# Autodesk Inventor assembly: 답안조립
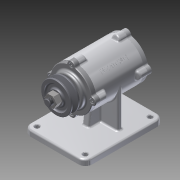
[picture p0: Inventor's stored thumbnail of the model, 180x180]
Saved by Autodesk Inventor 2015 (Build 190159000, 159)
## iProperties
Created: 2015-12
Part Number: 답안조립
Document SubType Name: Assembly
Designer: Administrator
Author: Administrator
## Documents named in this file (11)
- C:\Users\Administrator\Desktop\451207V1011\답안조립.iam
- C:\Users\Administrator\Desktop\451207V1011\V-벨트풀리.ipt
- C:\Users\Administrator\Desktop\451207V1011\너트 M12x1.25.ipt
- C:\Users\Administrator\Desktop\451207V1011\베어링 6204.ipt
- C:\Users\Administrator\Desktop\451207V1011\본체.ipt
- C:\Users\Administrator\Desktop\451207V1011\볼트 M4 x 12.ipt
- C:\Users\Administrator\Desktop\451207V1011\오일실.ipt
- C:\Users\Administrator\Desktop\451207V1011\축.ipt
- C:\Users\Administrator\Desktop\451207V1011\커버.ipt
- C:\Users\Administrator\Desktop\451207V1011\커버2.ipt
- C:\Users\Administrator\Desktop\451207V1011\키(4 x 4 x 12).ipt
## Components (6 placed, 5 different names)
1. V-벨트풀리:1
2. KS B 1012 클래스 1 일반 - 미터 M12x1.25:1 — 각도:3
3. KS B 2023 6204 - 20 x 47 x 14:1
4. KS B 1311 (I) 4 x 4 x 12:1
5. KS B 2023 6204 - 20 x 47 x 14:2
6. KS B 2804 D D - 20 32 8:2
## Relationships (1: Angle 1)
- 각도:3 [Angle]: KS B 1012 클래스 1 일반 - 미터 M12x1.25:1
